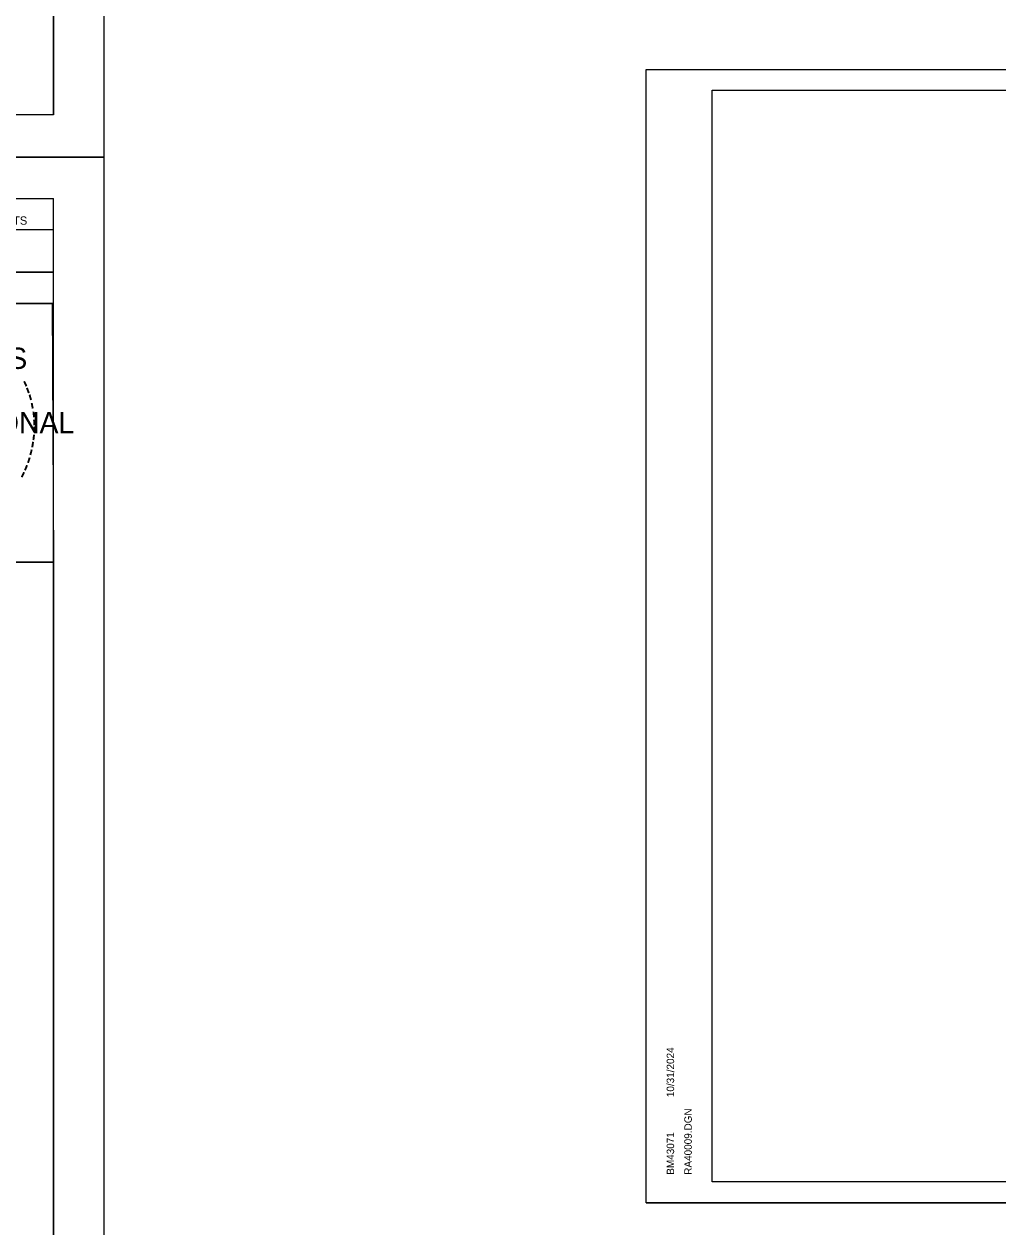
# Model space of a CAD drawing. Extents: x 1381471 to 1382703, y 370300 to 371487.
# Drawn here: x 1382292 to 1382383.6, y 370746.5 to 370859.7 of the extents above; entities that cross this region are included whole.
import ezdxf

# ---------------------------------------------------------------- set-up
doc = ezdxf.new("R2010")
doc.units = 0
for name, color, linetype in [('Level 26', 7, 'Continuous'), ('Level 45', 7, 'Continuous'), ('Level 6', 7, 'Continuous')]:
    doc.layers.add(name, color=color, linetype=linetype)

msp = doc.modelspace()

# ---------------------------------------------------------------- linework, layer by layer
at = {"layer": 'Level 26'}
for p, q in [((1382350.55, 370855.4), (1382517.22, 370855.4)), ((1382350.55, 370748.73), (1382517.22, 370748.73))]:
    msp.add_line(p, q, dxfattribs=at)
for points in [[(1382350.55, 370855.4), (1382517.22, 370855.4), (1382517.22, 370748.73), (1382350.55, 370748.73)], [(1382473.71, 370853.45), (1382483.52, 370853.45), (1382483.52, 370848.51), (1382491.58, 370848.51), (1382503.17, 370848.51), (1382503.17, 370836.34), (1382514.84, 370836.34), (1382514.84, 370750.72), (1382356.75, 370750.72), (1382356.75, 370853.45)]]:
    msp.add_lwpolyline(points, close=True, dxfattribs=at)
at = {"layer": 'Level 45'}
for p, q in [((1382294.79, 370851.12), (1382294.79, 371056.58)), ((1382294.79, 370851.12), (1381978.61, 370851.12)), ((1381966.21, 370847.14), (1382299.55, 370847.14)), ((1381966.21, 370847.14), (1382299.55, 370847.14)), ((1381978.61, 370843.24), (1382294.79, 370843.24)), ((1382294.79, 370637.78), (1382294.79, 370843.24)), ((1382294.79, 370840.3), (1382251.69, 370840.3)), ((1382294.79, 370840.32), (1382294.79, 370840.32)), ((1382294.79, 370836.3), (1382251.69, 370836.3)), ((1382254.65, 370836.3), (1382294.79, 370836.3)), ((1382294.79, 370833.36), (1382232.15, 370833.36))]:
    msp.add_line(p, q, dxfattribs=at)
for points in [[(1381966.21, 371060.47), (1382299.55, 371060.47), (1382299.55, 370847.14), (1381966.21, 370847.14)], [(1382212.53, 371056.58), (1382232.15, 371056.58), (1382232.15, 371046.7), (1382248.27, 371046.7), (1382271.46, 371046.7), (1382271.46, 371022.37), (1382294.79, 371022.37), (1382294.79, 370851.12), (1381978.61, 370851.12), (1381978.61, 371056.58)], [(1381966.21, 370847.14), (1382299.55, 370847.14), (1382299.55, 370633.8), (1381966.21, 370633.8)], [(1382212.53, 370843.24), (1382232.15, 370843.24), (1382232.15, 370833.36), (1382248.27, 370833.36), (1382271.46, 370833.36), (1382271.46, 370809.03), (1382294.79, 370809.03), (1382294.79, 370637.78), (1381978.61, 370637.78), (1381978.61, 370843.24)], [(1382271.46, 370833.36), (1382294.67, 370833.36), (1382294.79, 370809.03), (1382271.59, 370809.03)]]:
    msp.add_lwpolyline(points, close=True, dxfattribs=at)
at = {"layer": 'Level 6'}
for p, q in [((1382356.75, 370853.45), (1382514.84, 370853.45)), ((1382356.75, 370750.72), (1382356.75, 370853.45)), ((1382356.75, 370750.72), (1382356.75, 370750.72)), ((1382514.84, 370750.72), (1382356.75, 370750.72))]:
    msp.add_line(p, q, dxfattribs=at)

# ---------------------------------------------------------------- texts
at = {"layer": 'Level 45'}
for s, height, rotation, p in [('SHEETS', 0.782, 360, (1382288.15, 370840.78)), ('ARKANSAS', 2, 360, (1382277.77, 370827.21)), ('-', 1.6, 294.6628, (1382291.44, 370825.88)), ('-', 1.6, 290.5728, (1382291.69, 370825.3)), ('-', 1.6, 285.1233, (1382291.93, 370824.72)), ('PROFESSIONAL', 2, 360, (1382275.95, 370821.15)), ('-', 1.6, 280.5493, (1382292.13, 370823.98)), ('-', 1.6, 276.5962, (1382292.29, 370823.21)), ('-', 1.6, 274.3301, (1382292.35, 370822.49)), ('-', 1.6, 263.5172, (1382292.37, 370821.19)), ('-', 1.6, 269.9407, (1382292.38, 370821.86)), ('-', 1.6, 255.7626, (1382292.18, 370819.86)), ('-', 1.6, 260.9953, (1382292.29, 370820.54)), ('-', 1.6, 252.8681, (1382292, 370819.14)), ('-', 1.6, 244.6197, (1382291.52, 370817.84)), ('-', 1.6, 247.8887, (1382291.78, 370818.47))]:
    msp.add_text(s, height=height, rotation=rotation, dxfattribs=at).set_placement(p)
at = {"layer": 'Level 6'}
for s, p in [('10/31/2024', (1382353.18, 370758.68)), ('RA40009.DGN', (1382354.84, 370751.38)), ('BM43071', (1382353.18, 370751.38))]:
    msp.add_text(s, height=0.7, rotation=90, dxfattribs=at).set_placement(p)

doc.saveas('drawing.dxf')
